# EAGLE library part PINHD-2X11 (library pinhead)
PIN HEADER
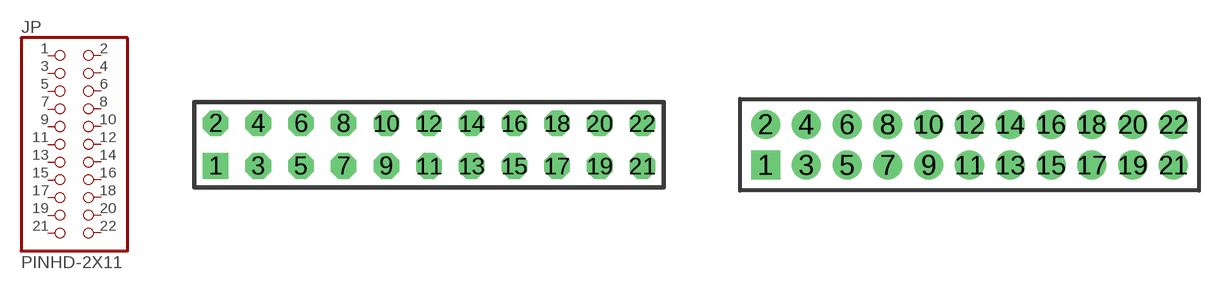
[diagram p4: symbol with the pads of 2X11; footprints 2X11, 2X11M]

Designator prefix JP

## PINHD-2X11  [2X11]
1  1  pas
2  2  pas
3  3  pas
4  4  pas
5  5  pas
6  6  pas
7  7  pas
8  8  pas
9  9  pas
10  10  pas
11  11  pas
12  12  pas
13  13  pas
14  14  pas
15  15  pas
16  16  pas
17  17  pas
18  18  pas
19  19  pas
20  20  pas
21  21  pas
22  22  pas

## PINHD-2X11M  [2X11M]
Pads as for 2X11

## Footprint 2X11 (pad centres in mm)
PIN HEADER - 0.1"
drill 1.016 square: 1 -12.7,-1.27
drill 1.016 octagon: 2 -12.7,1.27; 3 -10.16,-1.27; 4 -10.16,1.27; 5 -7.62,-1.27; 6 -7.62,1.27; 7 -5.08,-1.27; 8 -5.08,1.27; 9 -2.54,-1.27; 10 -2.54,1.27; 11 0,-1.27; 12 0,1.27; 13 2.54,-1.27; 14 2.54,1.27; 15 5.08,-1.27; 16 5.08,1.27; 17 7.62,-1.27; 18 7.62,1.27; 19 10.16,-1.27; 20 10.16,1.27; 21 12.7,-1.27; 22 12.7,1.27

## Footprint 2X11M (pad centres in mm)
PIN HEADER - 2MM"
drill 0.914 square: 1 -10,-1
drill 0.914 round: 2 -10,1; 3 -8,-1; 4 -8,1; 5 -6,-1; 6 -6,1; 7 -4,-1; 8 -4,1; 9 -2,-1; 10 -2,1; 11 0,-1; 12 0,1; 13 2,-1; 14 2,1; 15 4,-1; 16 4,1; 17 6,-1; 18 6,1; 19 8,-1; 20 8,1; 21 10,-1; 22 10,1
